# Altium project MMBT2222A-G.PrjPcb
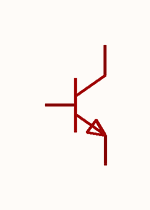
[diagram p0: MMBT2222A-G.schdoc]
1 sheet, 1 parts. Net scope: global (net labels, ports and power ports of the same name join across sheets).

## Sheet MMBT2222A-G.schdoc
size 127 x 101 mm

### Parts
Q?  mmbt2222a-g  [SOT-23-3_L2.9-W1.6-P1.90-LS2.8-BR]  (value not drawn)

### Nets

Not connected (* = marked no-connect by the designer): Q? 1(B) 2(E) 3(C)

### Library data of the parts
Q? = mmbt2222a-g: 晶体管类型:NPN;集电极电流(Ic):600mA;集射极击穿电压(Vceo):40V;耗散功率(Pd):300mW;直流电流增益(hFE):100;; Manufacturer: CJ(江苏长电/长晶); AddInBom: yes; ModelId: 89cb27a44ab2466697082bb9fd73a7d0; ModelName: SOT-23-3L_L2.9-W1.6-H1.1-LS2.8-P0.95; ModelTransform: 114.173,110.236,0,90,0,0,0,0,0; type: NPN; Current - Collector(Ic): 600mA; Collector - Emitter Voltage VCEO: 40V; Pd - Power Dissipation: 300mW; DC Current Gain: 100; Transition frequency(fT): 300MHz; Current - Collector Cutoff: 10nA; Vce Saturation(VCE(sat)): 1V; Emitter-Base Voltage(Vebo): 6V; Number: 1个NPN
